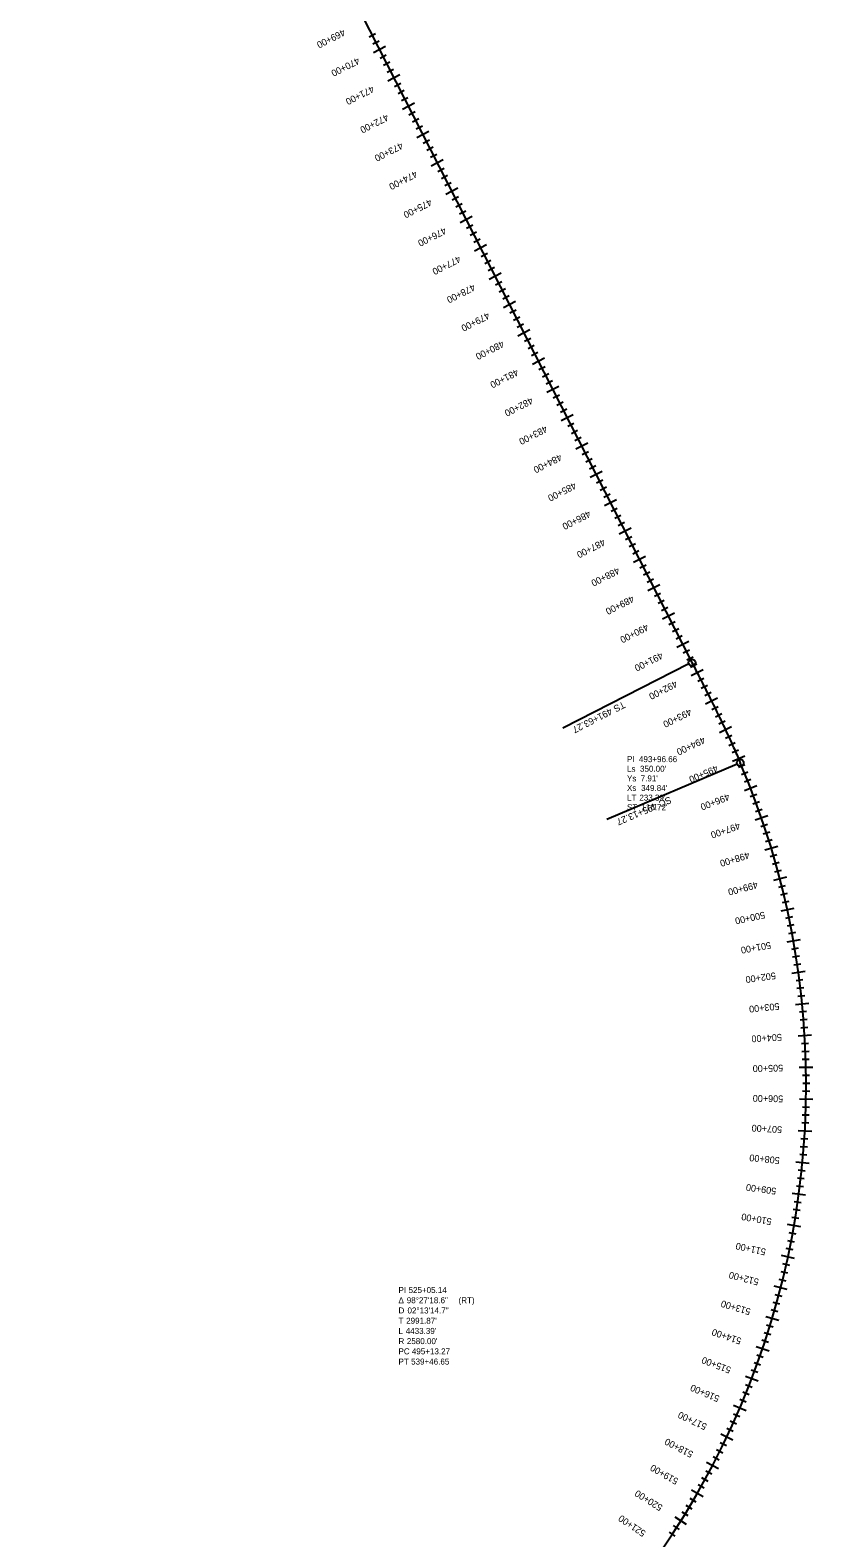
# Model space of a CAD drawing. Extents: x 2823077 to 2858057, y 1248786 to 1289821.
# Drawn here: x 2854367 to 2856830, y 1253494 to 1258236 of the extents above; entities that cross this region are included whole.
import ezdxf

# ---------------------------------------------------------------- set-up
doc = ezdxf.new("R2010")
doc.units = 0
for name, color, linetype in [('_CIVIL_CONSTRUCTION', 7, 'Continuous'), ('TL_Earth Shoulder Sub', 7, 'Continuous'), ('TL_End Condition Hinge', 7, 'Continuous'), ('TL_Pavement Centerline Sub', 7, 'Continuous'), ('TL_Pavement Edge Sub', 7, 'Continuous'), ('TL_Shoulder Edge', 7, 'Continuous'), ('TL_Shoulder Edge Sub', 7, 'Continuous')]:
    doc.layers.add(name, color=color, linetype=linetype)

msp = doc.modelspace()

# ---------------------------------------------------------------- linework, layer by layer
at = {"layer": '_CIVIL_CONSTRUCTION'}
msp.add_line((2854367.5, 1260328.9), (2856449.3, 1256246.9), dxfattribs=at)
msp.add_arc((2854228.6, 1254918), 2580, 284.6793, 23.1345, dxfattribs=at)
msp.add_arc((2854228.6, 1254918), 2580, 284.6793, 23.1345, dxfattribs=at)
msp.add_open_spline([(2856449.3, 1256246.9), (2856455.9, 1256233.9), (2856469.1, 1256208), (2856495.5, 1256155.9), (2856528.1, 1256090.7), (2856559.6, 1256024.9), (2856583.7, 1255971.8), (2856595.4, 1255945.1), (2856601.1, 1255931.7)], degree=3, dxfattribs=at)
msp.add_open_spline([(2856449.3, 1256246.9), (2856455.9, 1256233.9), (2856469.1, 1256208), (2856495.5, 1256155.9), (2856528.1, 1256090.7), (2856559.6, 1256024.9), (2856583.7, 1255971.8), (2856595.4, 1255945.1), (2856601.1, 1255931.7)], degree=3, dxfattribs=at)
at = {"layer": 'TL_Earth Shoulder Sub'}
for p, q in [((2856449.3, 1256246.9), (2856449.3, 1256246.9)), ((2856043, 1256039.8), (2856043, 1256039.8)), ((2856601.1, 1255931.7), (2856601.1, 1255931.7)), ((2856181.8, 1255752.5), (2856181.8, 1255752.5)), ((2856181.8, 1255752.5), (2856181.8, 1255752.5))]:
    msp.add_line(p, q, dxfattribs=at)
for centre in [(2856449.3, 1256246.9), (2856601.1, 1255931.7)]:
    msp.add_circle(centre, 10.7, dxfattribs=at)
at = {"layer": 'TL_Pavement Centerline Sub'}
for p, q in [((2855485.5, 1258183.8), (2855447.6, 1258164.5)), ((2855530.9, 1258094.7), (2855493.1, 1258075.4)), ((2855576.3, 1258005.6), (2855538.5, 1257986.3)), ((2855621.8, 1257916.5), (2855583.9, 1257897.2)), ((2855667.2, 1257827.4), (2855629.4, 1257808.1)), ((2855712.6, 1257738.3), (2855674.8, 1257719)), ((2855758.1, 1257649.3), (2855720.2, 1257630)), ((2855803.5, 1257560.2), (2855765.7, 1257540.9)), ((2855848.9, 1257471.1), (2855811.1, 1257451.8)), ((2855894.4, 1257382), (2855856.5, 1257362.7)), ((2855939.8, 1257292.9), (2855901.9, 1257273.6)), ((2855985.2, 1257203.8), (2855947.4, 1257184.5)), ((2856030.7, 1257114.7), (2855992.8, 1257095.5)), ((2856076.1, 1257025.7), (2856038.2, 1257006.4)), ((2856121.5, 1256936.6), (2856083.7, 1256917.3)), ((2856166.9, 1256847.5), (2856129.1, 1256828.2)), ((2856212.4, 1256758.4), (2856174.5, 1256739.1)), ((2856257.8, 1256669.3), (2856220, 1256650)), ((2856303.2, 1256580.2), (2856265.4, 1256560.9)), ((2856348.7, 1256491.2), (2856310.8, 1256471.9)), ((2856394.1, 1256402.1), (2856356.3, 1256382.8)), ((2856439.5, 1256313), (2856401.7, 1256293.7)), ((2856485, 1256223.9), (2856447.1, 1256204.6)), ((2856530.1, 1256134.4), (2856492, 1256115.5)), ((2856573.9, 1256044.1), (2856535.5, 1256025.9)), ((2856615.5, 1255952.4), (2856576.5, 1255935.5)), ((2856653.8, 1255859.1), (2856614.2, 1255843.7)), ((2856688.4, 1255764.4), (2856648.3, 1255750.6)), ((2856719.4, 1255668.5), (2856678.7, 1255656.2)), ((2856746.6, 1255571.4), (2856705.5, 1255560.7)), ((2856770, 1255473.3), (2856728.5, 1255464.2)), ((2856789.6, 1255374.4), (2856747.8, 1255367)), ((2856805.4, 1255274.8), (2856763.3, 1255269)), ((2856817.3, 1255174.7), (2856775, 1255170.5)), ((2856825.3, 1255074.2), (2856782.9, 1255071.7)), ((2856829.4, 1254973.5), (2856786.9, 1254972.6)), ((2856829.6, 1254872.7), (2856787.1, 1254873.4)), ((2856825.9, 1254771.9), (2856783.5, 1254774.3)), ((2856818.3, 1254671.4), (2856776, 1254675.4)), ((2856806.7, 1254571.2), (2856764.6, 1254576.9)), ((2856791.4, 1254471.6), (2856749.5, 1254478.9)), ((2856772.1, 1254372.6), (2856730.6, 1254381.5)), ((2856749.1, 1254274.4), (2856707.9, 1254284.9)), ((2856722.3, 1254177.3), (2856681.5, 1254189.3)), ((2856691.7, 1254081.2), (2856651.5, 1254094.8)), ((2856657.4, 1253986.4), (2856617.8, 1254001.6)), ((2856619.5, 1253892.9), (2856580.4, 1253909.7)), ((2856578, 1253801.1), (2856539.6, 1253819.3)), ((2856532.9, 1253710.9), (2856495.3, 1253730.6)), ((2856484.4, 1253622.5), (2856447.6, 1253643.6)), ((2856432.5, 1253536), (2856396.5, 1253558.6))]:
    msp.add_line(p, q, dxfattribs=at)
at = {"layer": 'TL_Pavement Edge Sub'}
for p, q in [((2855453.6, 1258223.6), (2855433.9, 1258213.6)), ((2855464.9, 1258201.3), (2855445.3, 1258191.3)), ((2855487.6, 1258156.8), (2855468, 1258146.8)), ((2855499, 1258134.5), (2855479.3, 1258124.5)), ((2855510.4, 1258112.3), (2855490.7, 1258102.2)), ((2855533.1, 1258067.7), (2855513.4, 1258057.7)), ((2855544.4, 1258045.4), (2855524.8, 1258035.4)), ((2855555.8, 1258023.2), (2855536.1, 1258013.1)), ((2855578.5, 1257978.6), (2855558.8, 1257968.6)), ((2855589.9, 1257956.4), (2855570.2, 1257946.3)), ((2855601.2, 1257934.1), (2855581.5, 1257924.1)), ((2855623.9, 1257889.5), (2855604.3, 1257879.5)), ((2855635.3, 1257867.3), (2855615.6, 1257857.2)), ((2855646.7, 1257845), (2855627, 1257835)), ((2855669.4, 1257800.5), (2855649.7, 1257790.4)), ((2855680.7, 1257778.2), (2855661.1, 1257768.2)), ((2855692.1, 1257755.9), (2855672.4, 1257745.9)), ((2855714.8, 1257711.4), (2855695.1, 1257701.3)), ((2855726.2, 1257689.1), (2855706.5, 1257679.1)), ((2855737.5, 1257666.8), (2855717.8, 1257656.8)), ((2855760.2, 1257622.3), (2855740.6, 1257612.3)), ((2855771.6, 1257600), (2855751.9, 1257590)), ((2855782.9, 1257577.8), (2855763.3, 1257567.7)), ((2855805.7, 1257533.2), (2855786, 1257523.2)), ((2855817, 1257510.9), (2855797.3, 1257500.9)), ((2855828.4, 1257488.7), (2855808.7, 1257478.6)), ((2855851.1, 1257444.1), (2855831.4, 1257434.1)), ((2855862.4, 1257421.9), (2855842.8, 1257411.8)), ((2855873.8, 1257399.6), (2855854.1, 1257389.6)), ((2855896.5, 1257355), (2855876.9, 1257345)), ((2855907.9, 1257332.8), (2855888.2, 1257322.7)), ((2855919.2, 1257310.5), (2855899.6, 1257300.5)), ((2855942, 1257266), (2855922.3, 1257255.9)), ((2855953.3, 1257243.7), (2855933.6, 1257233.7)), ((2855964.7, 1257221.4), (2855945, 1257211.4)), ((2855987.4, 1257176.9), (2855967.7, 1257166.8)), ((2855998.7, 1257154.6), (2855979.1, 1257144.6)), ((2856010.1, 1257132.3), (2855990.4, 1257122.3)), ((2856032.8, 1257087.8), (2856013.1, 1257077.8)), ((2856044.2, 1257065.5), (2856024.5, 1257055.5)), ((2856055.5, 1257043.2), (2856035.9, 1257033.2)), ((2856078.2, 1256998.7), (2856058.6, 1256988.7)), ((2856089.6, 1256976.4), (2856069.9, 1256966.4)), ((2856101, 1256954.2), (2856081.3, 1256944.1)), ((2856123.7, 1256909.6), (2856104, 1256899.6)), ((2856135, 1256887.4), (2856115.4, 1256877.3)), ((2856146.4, 1256865.1), (2856126.7, 1256855)), ((2856169.1, 1256820.5), (2856149.4, 1256810.5)), ((2856180.5, 1256798.3), (2856160.8, 1256788.2)), ((2856191.8, 1256776), (2856172.2, 1256766)), ((2856214.5, 1256731.5), (2856194.9, 1256721.4)), ((2856225.9, 1256709.2), (2856206.2, 1256699.2)), ((2856237.3, 1256686.9), (2856217.6, 1256676.9)), ((2856260, 1256642.4), (2856240.3, 1256632.3)), ((2856271.3, 1256620.1), (2856251.7, 1256610.1)), ((2856282.7, 1256597.8), (2856263, 1256587.8)), ((2856305.4, 1256553.3), (2856285.7, 1256543.3)), ((2856316.8, 1256531), (2856297.1, 1256521)), ((2856328.1, 1256508.7), (2856308.5, 1256498.7)), ((2856350.8, 1256464.2), (2856331.2, 1256454.2)), ((2856362.2, 1256441.9), (2856342.5, 1256431.9)), ((2856373.6, 1256419.7), (2856353.9, 1256409.6)), ((2856396.3, 1256375.1), (2856376.6, 1256365.1)), ((2856407.6, 1256352.8), (2856388, 1256342.8)), ((2856419, 1256330.6), (2856399.3, 1256320.5)), ((2856441.7, 1256286), (2856422, 1256276)), ((2856453.1, 1256263.8), (2856433.4, 1256253.7)), ((2856464.4, 1256241.5), (2856444.7, 1256231.5)), ((2856487.1, 1256196.9), (2856467.4, 1256186.9)), ((2856498.4, 1256174.6), (2856478.7, 1256164.6)), ((2856509.7, 1256152.2), (2856489.9, 1256142.3)), ((2856531.9, 1256107.4), (2856512.1, 1256097.6)), ((2856542.9, 1256084.9), (2856523.1, 1256075.2)), ((2856553.8, 1256062.3), (2856533.9, 1256052.8)), ((2856575.2, 1256016.9), (2856555.2, 1256007.7)), ((2856585.7, 1255994.1), (2856565.6, 1255985)), ((2856595.9, 1255971.2), (2856575.8, 1255962.3)), ((2856615.9, 1255925.2), (2856595.6, 1255916.6)), ((2856625.5, 1255902), (2856605.1, 1255893.6)), ((2856635, 1255878.7), (2856614.5, 1255870.5)), ((2856653.1, 1255831.9), (2856632.5, 1255824.1)), ((2856661.9, 1255808.4), (2856641.1, 1255800.8)), ((2856670.4, 1255784.8), (2856649.6, 1255777.4)), ((2856686.7, 1255737.3), (2856665.8, 1255730.3)), ((2856694.5, 1255713.4), (2856673.5, 1255706.6)), ((2856702.1, 1255689.5), (2856681.1, 1255682.9)), ((2856716.6, 1255641.4), (2856695.4, 1255635.2)), ((2856723.5, 1255617.3), (2856702.3, 1255611.3)), ((2856730.2, 1255593.1), (2856708.9, 1255587.3)), ((2856742.8, 1255544.5), (2856721.4, 1255539.1)), ((2856748.7, 1255520.1), (2856727.3, 1255514.9)), ((2856754.5, 1255495.6), (2856732.9, 1255490.7)), ((2856765.2, 1255446.6), (2856743.6, 1255442.1)), ((2856770.2, 1255422), (2856748.5, 1255417.7)), ((2856774.9, 1255397.3), (2856753.2, 1255393.2)), ((2856783.7, 1255347.9), (2856762, 1255344.2)), ((2856787.8, 1255323.1), (2856766, 1255319.6)), ((2856791.6, 1255298.3), (2856769.8, 1255295)), ((2856798.5, 1255248.5), (2856776.6, 1255245.7)), ((2856801.6, 1255223.6), (2856779.6, 1255221)), ((2856804.4, 1255198.7), (2856782.5, 1255196.3)), ((2856809.4, 1255148.7), (2856787.4, 1255146.7)), ((2856811.5, 1255123.7), (2856789.5, 1255121.9)), ((2856813.3, 1255098.6), (2856791.3, 1255097.1)), ((2856816.4, 1255048.5), (2856794.3, 1255047.4)), ((2856817.5, 1255023.4), (2856795.4, 1255022.5)), ((2856818.4, 1254998.4), (2856796.3, 1254997.7)), ((2856819.5, 1254948.2), (2856797.4, 1254947.9)), ((2856819.6, 1254923), (2856797.6, 1254923)), ((2856819.6, 1254897.9), (2856797.5, 1254898.1)), ((2856817.9, 1254822.6), (2856795.8, 1254823.5)), ((2856818.7, 1254847.7), (2856796.6, 1254848.3)), ((2856816.8, 1254797.6), (2856794.8, 1254798.6)), ((2856812.3, 1254722.4), (2856790.2, 1254724)), ((2856814, 1254747.4), (2856792, 1254748.9)), ((2856810.2, 1254697.4), (2856788.2, 1254699.2)), ((2856802.7, 1254622.4), (2856780.8, 1254624.9)), ((2856805.5, 1254647.4), (2856783.5, 1254649.7)), ((2856799.7, 1254597.5), (2856777.8, 1254600.2)), ((2856789.3, 1254522.9), (2856767.5, 1254526.3)), ((2856793.1, 1254547.7), (2856771.2, 1254550.9)), ((2856785.4, 1254498.1), (2856763.6, 1254501.7)), ((2856772.1, 1254424), (2856750.4, 1254428.2)), ((2856776.8, 1254448.6), (2856755.1, 1254452.6)), ((2856767.2, 1254399.3), (2856745.6, 1254403.7)), ((2856756.7, 1254350.2), (2856735.1, 1254355.1)), ((2856745.2, 1254301.3), (2856723.8, 1254306.6)), ((2856751.1, 1254325.8), (2856729.6, 1254330.8)), ((2856732.8, 1254252.7), (2856711.4, 1254258.4)), ((2856719.4, 1254204.3), (2856698.2, 1254210.4)), ((2856726.2, 1254228.5), (2856704.9, 1254234.3)), ((2856705.1, 1254156.2), (2856684, 1254162.7)), ((2856689.9, 1254108.3), (2856668.9, 1254115.2)), ((2856697.6, 1254132.2), (2856676.6, 1254138.9)), ((2856673.7, 1254060.8), (2856652.9, 1254068.1)), ((2856656.7, 1254013.5), (2856636, 1254021.3)), ((2856665.3, 1254037.1), (2856644.5, 1254044.6)), ((2856638.7, 1253966.7), (2856618.1, 1253974.8)), ((2856619.8, 1253920.1), (2856599.4, 1253928.6)), ((2856629.3, 1253943.4), (2856608.9, 1253951.7)), ((2856589.8, 1253851.1), (2856569.6, 1253860.2)), ((2856600, 1253874), (2856579.8, 1253882.9)), ((2856579.3, 1253828.2), (2856559.3, 1253837.5)), ((2856546.7, 1253760.4), (2856526.9, 1253770.2)), ((2856557.8, 1253782.9), (2856537.9, 1253792.6)), ((2856535.3, 1253738), (2856515.7, 1253748)), ((2856500.1, 1253671.4), (2856480.7, 1253682)), ((2856512, 1253693.5), (2856492.6, 1253703.9)), ((2856487.9, 1253649.5), (2856468.6, 1253660.3)), ((2856437, 1253562.9), (2856418.2, 1253574.4)), ((2856450, 1253584.3), (2856431.1, 1253595.7)), ((2856462.9, 1253605.9), (2856443.8, 1253617.1)), ((2856410.3, 1253520.3), (2856391.7, 1253532.2)), ((2856396.7, 1253499.2), (2856378.2, 1253511.3))]:
    msp.add_line(p, q, dxfattribs=at)
at = {"layer": 'TL_Shoulder Edge'}
for p, q in [((2856439.7, 1256242.1), (2856043, 1256039.8)), ((2856591.3, 1255927.5), (2856181.8, 1255752.5)), ((2856591.3, 1255927.5), (2856181.8, 1255752.5))]:
    msp.add_line(p, q, dxfattribs=at)

# ---------------------------------------------------------------- texts
at = {"layer": 'TL_Earth Shoulder Sub'}
for s, rotation, p in [('491+63.27', 207.0208, (2856191.8, 1256104.4)), ('TS', 207.0208, (2856232.6, 1256125.2)), ('495+13.27', 203.1345, (2856334.6, 1255806.9)), ('495+13.27', 203.1345, (2856334.6, 1255806.9)), ('SC', 203.1345, (2856379.1, 1255825.9)), ('SC', 203.1345, (2856379.1, 1255825.9))]:
    msp.add_text(s, height=21.36, rotation=rotation, dxfattribs=at).set_placement(p)
at = {"layer": 'TL_End Condition Hinge'}
for s, rotation, p in [('469+00', 207.0208, (2855352, 1258239.9)), ('470+00', 207.0208, (2855397.5, 1258150.8)), ('471+00', 207.0208, (2855442.9, 1258061.7)), ('472+00', 207.0208, (2855488.3, 1257972.6)), ('473+00', 207.0208, (2855533.8, 1257883.6)), ('474+00', 207.0208, (2855579.2, 1257794.5)), ('475+00', 207.0208, (2855624.6, 1257705.4)), ('476+00', 207.0208, (2855670.1, 1257616.3)), ('477+00', 207.0208, (2855715.5, 1257527.2)), ('478+00', 207.0208, (2855760.9, 1257438.1)), ('479+00', 207.0208, (2855806.4, 1257349.1)), ('480+00', 207.0208, (2855851.8, 1257260)), ('481+00', 207.0208, (2855897.2, 1257170.9)), ('482+00', 207.0208, (2855942.7, 1257081.8)), ('483+00', 207.0208, (2855988.1, 1256992.7)), ('484+00', 207.0208, (2856033.5, 1256903.6)), ('485+00', 207.0208, (2856078.9, 1256814.6)), ('486+00', 207.0208, (2856124.4, 1256725.5)), ('487+00', 207.0208, (2856169.8, 1256636.4)), ('488+00', 207.0208, (2856215.2, 1256547.3)), ('489+00', 207.0208, (2856260.7, 1256458.2)), ('490+00', 207.0208, (2856306.1, 1256369.1)), ('491+00', 207.0208, (2856351.5, 1256280)), ('492+00', 206.978, (2856396.9, 1256191)), ('493+00', 206.4277, (2856441.7, 1256102.4)), ('494+00', 205.2429, (2856485, 1256013.9)), ('495+00', 203.4235, (2856525.6, 1255925)), ('496+00', 201.2084, (2856562.9, 1255835.2)), ('497+00', 198.9876, (2856596.7, 1255744.1)), ('498+00', 196.7668, (2856626.9, 1255651.7)), ('499+00', 194.5461, (2856653.5, 1255558.2)), ('500+00', 192.3253, (2856676.5, 1255463.8)), ('501+00', 190.1045, (2856695.8, 1255368.5)), ('502+00', 187.8838, (2856711.4, 1255272.6)), ('503+00', 185.663, (2856723.3, 1255176.1)), ('504+00', 183.4422, (2856731.4, 1255079.2)), ('505+00', 181.2215, (2856735.8, 1254982.1)), ('506+00', 179.0007, (2856736.4, 1254884.9)), ('507+00', 176.7799, (2856733.2, 1254787.8)), ('508+00', 174.5592, (2856726.3, 1254690.8)), ('509+00', 172.3384, (2856715.6, 1254594.2)), ('510+00', 170.1176, (2856701.2, 1254498.1)), ('511+00', 167.8969, (2856683.1, 1254402.6)), ('512+00', 165.6761, (2856661.3, 1254307.8)), ('513+00', 163.4553, (2856635.8, 1254214)), ('514+00', 161.2346, (2856606.7, 1254121.3)), ('515+00', 159.0138, (2856574.1, 1254029.7)), ('516+00', 156.793, (2856537.9, 1253939.5)), ('517+00', 154.5723, (2856498.2, 1253850.8)), ('518+00', 152.3515, (2856455.2, 1253763.6)), ('519+00', 150.1307, (2856408.8, 1253678.2)), ('520+00', 147.91, (2856359.1, 1253594.7)), ('521+00', 145.6892, (2856306.2, 1253513.1))]:
    msp.add_text(s, height=21.26, rotation=rotation, dxfattribs=at).set_placement(p)
at = {"layer": 'TL_Shoulder Edge Sub'}
for s, height, p in [('PI ', 18.9, (2856244.9, 1255933.4)), ('493+96.66', 18.9, (2856282.6, 1255933.4)), ('Ls ', 18.9, (2856244.9, 1255903.2)), ("350.00'", 18.9, (2856285.9, 1255903.2)), ('Ys ', 18.9, (2856244.9, 1255872.9)), ('Xs ', 18.9, (2856244.9, 1255842.7)), ("7.91'", 18.9, (2856288.1, 1255872.9)), ("349.84'", 18.9, (2856289.3, 1255842.7)), ('LT ', 18.9, (2856244.9, 1255812.4)), ("233.39'", 18.9, (2856283.8, 1255812.4)), ('ST ', 18.9, (2856244.9, 1255782.2)), ("116.72'", 18.9, (2856290.3, 1255782.2)), ('Δ ', 18.9, (2855526.2, 1254231.5)), ('PI ', 18.9, (2855526.2, 1254263.6)), ('98°27\'18.6"', 18.898, (2855552.2, 1254231.5)), ('525+05.14', 18.9, (2855557.8, 1254263.6)), (' (RT)', 18.9, (2855708, 1254231.5)), ('D ', 18.9, (2855526.2, 1254199.4)), ('02°13\'14.7"', 18.898, (2855554.4, 1254199.4)), ('T ', 18.9, (2855526.2, 1254167.2)), ('L ', 18.9, (2855526.2, 1254135.1)), ("4433.39'", 18.9, (2855548.9, 1254135.1)), ("2991.87'", 18.9, (2855550.3, 1254167.2)), ('R ', 18.9, (2855526.2, 1254103)), ("2580.00'", 18.9, (2855552.5, 1254103)), ('PC ', 18.9, (2855526.2, 1254070.9)), ('PT ', 18.9, (2855526.2, 1254038.7)), ('539+46.65', 18.9, (2855565.9, 1254038.7)), ('495+13.27', 18.9, (2855568.2, 1254070.9))]:
    msp.add_text(s, height=height, dxfattribs=at).set_placement(p)

doc.saveas('drawing.dxf')
